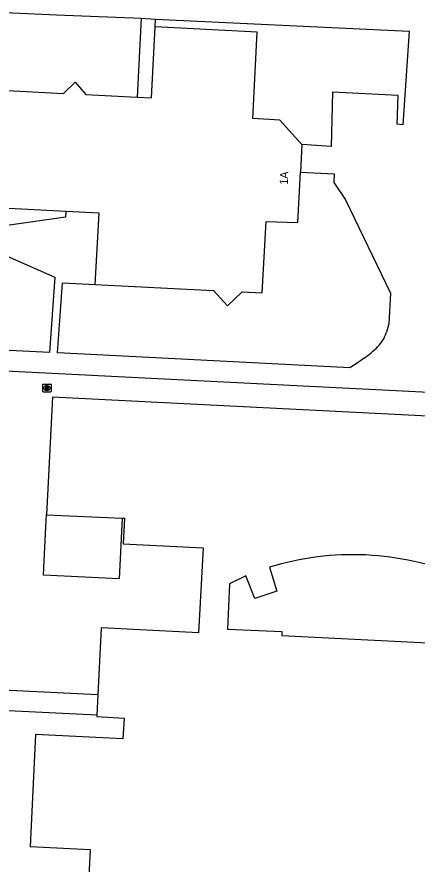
# Model space of a CAD drawing. Extents: x 161761 to 162722, y 384793 to 385405.
# Drawn here: x 161913.2 to 161962.4, y 385048.1 to 385152.1 of the extents above; entities that cross this region are included whole.
import ezdxf

# ---------------------------------------------------------------- set-up
doc = ezdxf.new("R2010")
doc.units = 0
for name, color, linetype in [('IMGEO_Pand', 7, 'Continuous'), ('IMGEO_Pand_nummerreeks', 7, 'Continuous'), ('IMGEO_Rijbaan_lokaal_open', 7, 'Continuous'), ('IMGEO_Rioolput', 7, 'Continuous'), ('IMGEO_Voetpad_open', 7, 'Continuous')]:
    doc.layers.add(name, color=color, linetype=linetype)

msp = doc.modelspace()

# ---------------------------------------------------------------- linework, layer by layer
at = {"layer": 'IMGEO_Pand'}
for points in [[(161927.98, 385142.25), (161929.77, 385142.16), (161930.21, 385150.85)], [(161948.23, 385136.42), (161945.51, 385139.43), (161942.2, 385139.61), (161942.73, 385150.22), (161930.21, 385150.85)], [(161919.24, 385128.21), (161902.88, 385129.08), (161903.05, 385132.18), (161896.04, 385132.58), (161896.4, 385139.57), (161896.63, 385143.83), (161903.61, 385143.48), (161918.94, 385142.7), (161920.38, 385144.06), (161921.68, 385142.57), (161927.98, 385142.25)], [(161948.23, 385136.42), (161948.06, 385133.03)], [(161922.82, 385119.26), (161937.35, 385118.51), (161939.07, 385116.65), (161940.9, 385118.33), (161943.34, 385118.24), (161943.83, 385126.99), (161947.74, 385126.85), (161948.06, 385133.03)], [(161922.82, 385119.26), (161923.31, 385127.99), (161919.24, 385128.21)], [(161977.45, 385102.4), (161917.59, 385105.41), (161916.87, 385091)], [(161916.87, 385091), (161926.17, 385090.6)], [(161926.17, 385090.6), (161926.44, 385090.58), (161926.28, 385087.45), (161936.08, 385086.96), (161935.54, 385076.52), (161923.58, 385077.12), (161923.17, 385068.89)], [(161944.24, 385084.57), (161945.13, 385081.64), (161942.46, 385080.71), (161941.34, 385083.49), (161939.31, 385082.54), (161939.07, 385076.98), (161945.75, 385076.68), (161945.74, 385076.2), (161968.52, 385075.03), (161968.53, 385075.54), (161972.21, 385075.37), (161972.51, 385080.92), (161970.46, 385082.04), (161969.17, 385079.37), (161966.48, 385080.57), (161967.73, 385083.47)], [(161923.17, 385068.89), (161923.04, 385066.46)], [(161923.04, 385066.46), (161923.03, 385066.26), (161926.41, 385066.06), (161926.25, 385063.51), (161915.52, 385064.04), (161914.85, 385050.3), (161922.24, 385049.93), (161921.94, 385044.12), (161917.43, 385044.35), (161916.69, 385030.03)]]:
    msp.add_lwpolyline(points, dxfattribs=at)
msp.add_arc((161954.46, 385051.32), 34.78, 67.5709, 107.0866, dxfattribs=at)
at = {"layer": 'IMGEO_Rijbaan_lokaal_open'}
for points in [[(161923.17, 385068.89), (161902.28, 385069.94)], [(161916.69, 385030.03), (161914.96, 385030.12), (161908.76, 385030.44), (161905.01, 385034.49), (161905.15, 385037.28), (161909.3, 385041.09), (161914.23, 385040.84), (161914.47, 385045.67), (161901.52, 385046.33), (161902.42, 385063.98), (161909.48, 385063.64), (161909.64, 385067.1), (161923.04, 385066.46)]]:
    msp.add_lwpolyline(points, dxfattribs=at)
at = {"layer": 'IMGEO_Rioolput'}
for p, q in [((161916.42, 385106.12), (161916.42, 385106.97)), ((161916.49, 385107.04), (161917.34, 385107.04)), ((161916.9, 385106.82), (161916.93, 385106.82)), ((161916.93, 385106.26), (161916.9, 385106.26)), ((161917.42, 385106.97), (161917.42, 385106.12)), ((161917.34, 385106.04), (161916.49, 385106.04))]:
    msp.add_line(p, q, dxfattribs=at)
for points in [[(161916.42, 385106.12), (161916.42, 385106.97)], [(161916.49, 385107.04), (161917.34, 385107.04)], [(161917, 385106.74), (161916.75, 385106.74), (161916.75, 385106.34)], [(161916.75, 385106.34), (161916.88, 385106.34), (161916.88, 385106.5), (161916.89, 385106.5)], [(161916.93, 385106.66), (161916.88, 385106.66), (161916.88, 385106.58)], [(161916.88, 385106.58), (161916.93, 385106.58)], [(161916.93, 385106.47), (161917.01, 385106.34), (161917.14, 385106.34), (161917.08, 385106.47)], [(161917.42, 385106.97), (161917.42, 385106.12)], [(161917.34, 385106.04), (161916.49, 385106.04)]]:
    msp.add_lwpolyline(points, dxfattribs=at)
for centre, radius, start, end in [((161916.49, 385106.97), 0.0765, 91.552, 178.448), ((161916.49, 385106.97), 0.0765, 91.552, 178.448), ((161916.49, 385106.12), 0.0765, 181.552, 268.448), ((161916.49, 385106.12), 0.0765, 181.552, 268.448), ((161916.89, 385106.45), 0.0533, 26.0293, 88.6989), ((161916.94, 385106.56), 0.0964, 77.0061, 93.1865), ((161916.91, 385106.77), 0.19, 274.7715, 282.9687), ((161916.95, 385106.62), 0.0378, 276.6634, 79.6772), ((161917, 385106.63), 0.109, 350.3612, 89.416), ((161917, 385106.63), 0.112, 277.5842, 350.9817), ((161916.99, 385106.41), 0.108, 29.5134, 73.7905), ((161917.34, 385106.97), 0.0765, 1.552, 88.448), ((161917.34, 385106.97), 0.0765, 1.552, 88.448), ((161917.34, 385106.12), 0.0765, 271.552, 358.448), ((161917.34, 385106.12), 0.0765, 271.552, 358.448)]:
    msp.add_arc(centre, radius, start, end, dxfattribs=at)
for centre, major_axis, ratio, start_param, end_param in [((161916.9, 385106.54), (-0.387, 0.002), 0.722429, 4.712389, 7.853982), ((161916.93, 385106.54), (-0.39, 0.002), 0.717154, 1.570796, 4.712389)]:
    msp.add_ellipse(centre, major_axis=major_axis, ratio=ratio, start_param=start_param, end_param=end_param, dxfattribs=at)
at = {"layer": 'IMGEO_Voetpad_open'}
for points in [[(161908.14, 385152.77), (161918.08, 385152.35), (161925.36, 385152.04), (161927.52, 385151.95), (161928.47, 385151.91)], [(161928.47, 385151.91), (161927.98, 385142.25)], [(161928.47, 385151.91), (161930.25, 385151.82)], [(161930.21, 385150.85), (161930.25, 385151.82)], [(161930.25, 385151.82), (161961.39, 385150.32), (161960.61, 385138.85), (161959.91, 385138.9), (161960.05, 385142.45), (161951.97, 385142.86), (161951.8, 385136.16), (161948.23, 385136.42)], [(161948.06, 385133.03), (161952.17, 385132.81), (161952.14, 385131.77), (161953.56, 385129.64), (161959.09, 385118.2), (161958.88, 385114.43), (161958.61, 385113.39)], [(161919.24, 385128.21), (161919.21, 385127.53), (161911.18, 385126.36), (161894.35, 385127.12)], [(161910.1, 385123.22), (161910.96, 385123.18), (161917.9, 385120.15), (161917.25, 385110.9), (161905.69, 385111.49)], [(161955.86, 385110.23), (161954.99, 385109.61), (161954.1, 385109.02), (161923.88, 385110.56), (161918.22, 385110.85), (161918.83, 385119.45), (161922.82, 385119.26)], [(161906.14, 385108.94), (161977.6, 385105.33)], [(161926.17, 385090.6), (161925.8, 385083.13), (161916.49, 385083.6), (161916.54, 385084.5), (161916.8, 385089.51), (161916.87, 385091)]]:
    msp.add_lwpolyline(points, dxfattribs=at)
for centre, radius, start, end in [((161954.16, 385114.9), 4.71, 315.3958, 341.2395), ((161949.2, 385119.92), 11.76, 304.4887, 314.9652)]:
    msp.add_arc(centre, radius, start, end, dxfattribs=at)

# ---------------------------------------------------------------- texts
at = {"layer": 'IMGEO_Pand_nummerreeks'}
msp.add_text('1A', height=1, rotation=87.0495, dxfattribs=at).set_placement((161946.48, 385131.47))

doc.saveas('drawing.dxf')
